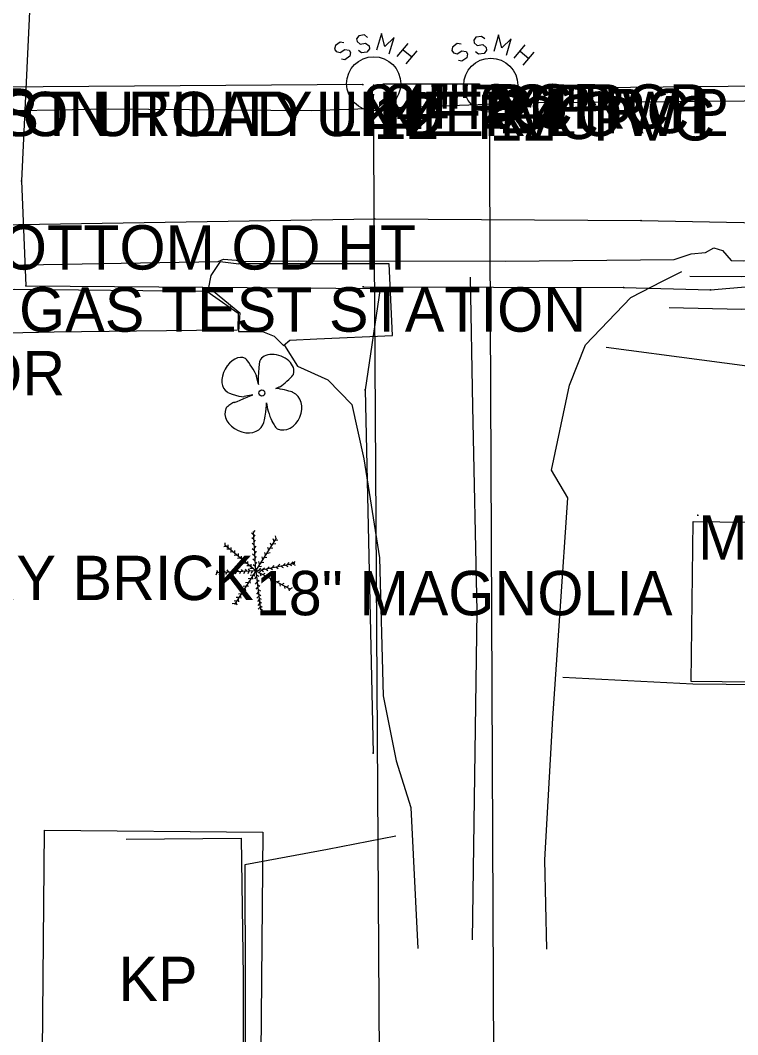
# Model space of a CAD drawing. Extents: x 1304270 to 1306561, y 1876019 to 1876752.
# Drawn here: x 1306257.2 to 1306338, y 1876310 to 1876424.3 of the extents above; entities that cross this region are included whole.
import ezdxf

# ---------------------------------------------------------------- set-up
doc = ezdxf.new("R2010")
doc.units = 0
for name, color, linetype in [('S_BUILDING', 7, 'Continuous'), ('S_BUILDING_ANNOT', 7, 'Continuous'), ('S_DRIVEWAY', 7, 'Continuous'), ('S_EDGE_CONCRETE', 7, 'Continuous'), ('S_EDGE_PAVEMENT', 7, 'Continuous'), ('S_ELECTRIC_UTILITIES_ANNOT', 7, 'Continuous'), ('S_FENCE_ANNOT', 7, 'Continuous'), ('S_FIBER_OPTIC_CABLE', 7, 'Continuous'), ('S_GAS_UTILITIES', 7, 'Continuous'), ('S_MANHOLE_ANNOT', 7, 'Continuous'), ('S_MISC_STRUCTURES_ANNOT', 7, 'Continuous'), ('S_MSC_PT_SYM', 7, 'Continuous'), ('S_PAVEMENT_CROWN', 7, 'Continuous'), ('S_SANITARY_SEWER', 7, 'Continuous'), ('S_SANITARY_SEWER_ANNOT', 7, 'Continuous'), ('S_SIDEWALK', 7, 'Continuous'), ('S_SURVEY_TEXT_ANNOT', 7, 'Continuous'), ('S_TREE', 7, 'Continuous'), ('S_TREE_ANNOT', 7, 'Continuous'), ('S_UTL_PT_SYM', 7, 'Continuous')]:
    doc.layers.add(name, color=color, linetype=linetype)

msp = doc.modelspace()

# ---------------------------------------------------------------- linework, layer by layer
at = {"layer": 'S_BUILDING'}
for points in [[(1306332.98, 1876367.83), (1306353.96, 1876367.59), (1306353.76, 1876349.58), (1306332.78, 1876349.82)], [(1306284.18, 1876299.56), (1306259.59, 1876299.78), (1306259.89, 1876333.06), (1306284.48, 1876332.84)]]:
    msp.add_lwpolyline(points, close=True, dxfattribs=at)
at = {"layer": 'S_DRIVEWAY'}
for points in [[(1306323.18, 1876387.47), (1306344.74, 1876384.62), (1306356.72, 1876379.57), (1306356.54, 1876363.18), (1306355.17, 1876349.22), (1306351.78, 1876349.32), (1306332.95, 1876349.51), (1306318.29, 1876350.28)], [(1306299.5, 1876332.4), (1306291.78, 1876330.88), (1306282.48, 1876329.17), (1306282.52, 1876315.62), (1306282.56, 1876302.07), (1306291.83, 1876303.11), (1306298.15, 1876300.65)]]:
    msp.add_lwpolyline(points, dxfattribs=at)
at = {"layer": 'S_EDGE_CONCRETE'}
for points in [[(1306279.7, 1876397.13), (1306278.64, 1876395.57), (1306278.32, 1876394.02), (1306278.93, 1876393.81), (1306281.92, 1876391.36), (1306281.76, 1876389.26), (1306284.47, 1876389.24), (1306285.76, 1876388.71), (1306286.81, 1876387.68), (1306287.53, 1876388.28), (1306290.57, 1876388.42), (1306299.12, 1876388.8), (1306298.72, 1876396.86), (1306288.66, 1876396.89), (1306281.81, 1876396.86)], [(1306279.7, 1876397.13), (1306281.81, 1876396.86)], [(1306269.08, 1876332.06), (1306282.06, 1876332.17), (1306282.27, 1876316.57), (1306282.31, 1876300.9)]]:
    msp.add_lwpolyline(points, dxfattribs=at)
at = {"layer": 'S_EDGE_PAVEMENT'}
for points in [[(1306165.48, 1876396.19), (1306188.31, 1876396.43), (1306201.55, 1876396.99), (1306203.51, 1876397.54), (1306207.41, 1876397.36), (1306207.63, 1876397.16), (1306215.41, 1876396.62), (1306234.61, 1876396.75), (1306255.38, 1876396.73), (1306279.47, 1876397.14), (1306280.07, 1876397.39), (1306281.48, 1876397.3), (1306281.94, 1876397.15), (1306288.47, 1876397.22), (1306311.84, 1876397.17), (1306330.84, 1876397.38), (1306332.77, 1876398.02), (1306334.38, 1876398.14), (1306335.31, 1876398.67), (1306336.28, 1876398.38), (1306337.28, 1876397.24), (1306338.63, 1876397.21), (1306354.54, 1876397.37)], [(1306316.5, 1876319.67), (1306316.26, 1876329.73), (1306317.19, 1876345.69), (1306318.01, 1876357.74), (1306318.87, 1876370.51), (1306317.01, 1876373.62), (1306319.05, 1876383.21), (1306320.86, 1876387.76), (1306325.95, 1876393.07), (1306329.55, 1876394.92), (1306331.7, 1876396)], [(1306286.94, 1876387.67), (1306288.39, 1876385.33), (1306291.82, 1876383.82), (1306294.54, 1876381.01), (1306295.87, 1876374.92), (1306297.65, 1876363.74), (1306298.05, 1876348.2), (1306299.51, 1876340.88), (1306301.19, 1876335.62), (1306301.96, 1876319.75)]]:
    msp.add_lwpolyline(points, dxfattribs=at)
at = {"layer": 'S_FIBER_OPTIC_CABLE'}
for p, q in [((1306252.11, 1876401.25), (1306297.1, 1876401.93)), ((1306297.1, 1876401.93), (1306327.13, 1876401.75)), ((1306327.13, 1876401.75), (1306345.07, 1876401.41))]:
    msp.add_line(p, q, dxfattribs=at)
at = {"layer": 'S_GAS_UTILITIES'}
for p, q in [((1306258.43, 1876430.5), (1306257.31, 1876406.22)), ((1306257.31, 1876406.22), (1306257.8, 1876394.4)), ((1306257.8, 1876394.4), (1306297.73, 1876394.08)), ((1306295.81, 1876394.3), (1306325.16, 1876394.21)), ((1306297.73, 1876394.08), (1306296.02, 1876382.69)), ((1306325.16, 1876394.21), (1306334.96, 1876393.93)), ((1306334.96, 1876393.93), (1306346.57, 1876394.94)), ((1306296.02, 1876382.69), (1306296.93, 1876341.76))]:
    msp.add_line(p, q, dxfattribs=at)
at = {"layer": 'S_MSC_PT_SYM'}
msp.add_lwpolyline([(1306333.53, 1876368.54), (1306333.53, 1876368.59), (1306333.53, 1876368.54), (1306333.48, 1876368.54), (1306333.53, 1876368.54), (1306333.53, 1876368.49), (1306333.53, 1876368.54), (1306333.58, 1876368.54)], dxfattribs=at)
at = {"layer": 'S_PAVEMENT_CROWN'}
for points in [[(1306053.64, 1876411.74), (1306078.45, 1876411.98), (1306096.34, 1876412.19), (1306114.22, 1876412.39), (1306129.3, 1876412.61), (1306144.38, 1876412.83), (1306159.45, 1876413.06), (1306174.53, 1876413.28), (1306194.7, 1876413.58), (1306214.87, 1876413.88), (1306234.9, 1876413.74), (1306250.98, 1876414.03), (1306267.06, 1876414.33), (1306289.97, 1876414.14), (1306302.49, 1876414.59), (1306315, 1876415.05), (1306334.8, 1876415.21), (1306354.59, 1876415.38)], [(1306308.12, 1876320.71), (1306308.39, 1876339.22), (1306308.66, 1876357.73), (1306308.15, 1876380.81), (1306307.91, 1876395.39)]]:
    msp.add_lwpolyline(points, dxfattribs=at)
at = {"layer": 'S_SANITARY_SEWER'}
for p, q in [((1306292.67, 1876421.46), (1306292.59, 1876421.07)), ((1306293.21, 1876421.85), (1306292.67, 1876421.46)), ((1306293.64, 1876421.77), (1306293.21, 1876421.85)), ((1306299.64, 1876420.22), (1306300.88, 1876421.69)), ((1306306.4, 1876421.69), (1306305.86, 1876421.3)), ((1306306.83, 1876421.61), (1306306.4, 1876421.69)), ((1306312.83, 1876420.06), (1306314.07, 1876421.54)), ((1306292.59, 1876421.07), (1306292.78, 1876420.8)), ((1306292.78, 1876420.8), (1306293.21, 1876420.69)), ((1306293.21, 1876420.69), (1306293.75, 1876421.03)), ((1306293.75, 1876421.03), (1306294.22, 1876420.96)), ((1306294.22, 1876420.96), (1306294.37, 1876420.69)), ((1306294.37, 1876420.69), (1306294.3, 1876420.26)), ((1306300.3, 1876421), (1306301.27, 1876420.18)), ((1306301.85, 1876420.88), (1306300.61, 1876419.41)), ((1306305.86, 1876421.3), (1306305.78, 1876420.92)), ((1306305.78, 1876420.92), (1306305.97, 1876420.64)), ((1306305.97, 1876420.64), (1306306.4, 1876420.53)), ((1306306.4, 1876420.53), (1306306.94, 1876420.88)), ((1306306.94, 1876420.88), (1306307.41, 1876420.8)), ((1306307.41, 1876420.8), (1306307.56, 1876420.53)), ((1306307.56, 1876420.53), (1306307.48, 1876420.1)), ((1306313.49, 1876420.84), (1306314.46, 1876420.02)), ((1306315.04, 1876420.72), (1306313.8, 1876419.25)), ((1306293.75, 1876419.87), (1306293.37, 1876419.95)), ((1306294.3, 1876420.26), (1306293.75, 1876419.87)), ((1306306.94, 1876419.71), (1306306.55, 1876419.79)), ((1306307.48, 1876420.1), (1306306.94, 1876419.71)), ((1306535.55, 1876418.78), (1306311.23, 1876416.59)), ((1306295.77, 1876417.07), (1306233.29, 1876416.64)), ((1306308.91, 1876417.1), (1306298.08, 1876417.12)), ((1306298.44, 1876181.2), (1306296.96, 1876415.93)), ((1306311.04, 1876183.54), (1306310.05, 1876415.77))]:
    msp.add_line(p, q, dxfattribs=at)
for points in [[(1306296.31, 1876422.39), (1306295.96, 1876422.66), (1306295.3, 1876422.58), (1306295.07, 1876422.24), (1306295.11, 1876421.93), (1306295.46, 1876421.62), (1306296.08, 1876421.73), (1306296.47, 1876421.42), (1306296.5, 1876421.11), (1306296.23, 1876420.72), (1306295.61, 1876420.65), (1306295.26, 1876420.92)], [(1306298.75, 1876420.53), (1306299.29, 1876422.39), (1306298.25, 1876421.38), (1306297.86, 1876422.82), (1306297.32, 1876420.96)], [(1306311.94, 1876420.37), (1306312.48, 1876422.23), (1306311.44, 1876421.23), (1306311.05, 1876422.66), (1306310.51, 1876420.8)], [(1306309.5, 1876422.23), (1306309.15, 1876422.5), (1306308.49, 1876422.43), (1306308.26, 1876422.08), (1306308.3, 1876421.77), (1306308.65, 1876421.46), (1306309.27, 1876421.57), (1306309.65, 1876421.26), (1306309.69, 1876420.95), (1306309.42, 1876420.57), (1306308.8, 1876420.49), (1306308.45, 1876420.76)]]:
    msp.add_lwpolyline(points, dxfattribs=at)
for centre in [(1306296.99, 1876417.16), (1306310.18, 1876417)]:
    msp.add_circle(centre, 3.05, dxfattribs=at)
at = {"layer": 'S_SIDEWALK'}
for points in [[(1306332.6, 1876395.5), (1306338.44, 1876395.45), (1306348.81, 1876395.93), (1306349.98, 1876395.68), (1306357.8, 1876395.81)], [(1306218.73, 1876393.56), (1306242.23, 1876393.89), (1306246.62, 1876393.94), (1306256.53, 1876394.01), (1306278.18, 1876393.8), (1306278.83, 1876393.36), (1306281.72, 1876391.3), (1306281.69, 1876389.49)], [(1306330.28, 1876391.97), (1306338.44, 1876391.76), (1306349.3, 1876391.86), (1306357.11, 1876391.89)], [(1306218.81, 1876388.57), (1306242.93, 1876388.89), (1306246.78, 1876388.93), (1306260.98, 1876389.2), (1306270.25, 1876389.34), (1306277.02, 1876389.42), (1306281.65, 1876389.43)]]:
    msp.add_lwpolyline(points, dxfattribs=at)
at = {"layer": 'S_TREE'}
for p, q in [((1306284.02, 1876383.3), (1306283.78, 1876384.19)), ((1306285.97, 1876382.84), (1306286.35, 1876383)), ((1306283.37, 1876382.13), (1306282.4, 1876381.92)), ((1306284.91, 1876381.2), (1306284.99, 1876380.76)), ((1306283.44, 1876366.36), (1306283.22, 1876366.56)), ((1306283.7, 1876362.28), (1306283.43, 1876366.71)), ((1306283.44, 1876366.61), (1306283.63, 1876366.84)), ((1306280.27, 1876365.16), (1306280.27, 1876365.46)), ((1306283.47, 1876365.8), (1306283.25, 1876365.99)), ((1306283.5, 1876365.22), (1306283.28, 1876365.42)), ((1306283.47, 1876366.13), (1306283.65, 1876366.36)), ((1306283.5, 1876365.53), (1306283.69, 1876365.76)), ((1306283.7, 1876362.28), (1306286.04, 1876365.96)), ((1306285.47, 1876365.14), (1306285.38, 1876365.42)), ((1306285.77, 1876365.59), (1306285.68, 1876365.88)), ((1306285.9, 1876365.75), (1306286.2, 1876365.79)), ((1306286.01, 1876365.93), (1306285.92, 1876366.22)), ((1306280.41, 1876365.02), (1306280.11, 1876364.98)), ((1306283.7, 1876362.28), (1306280.23, 1876365.19)), ((1306280.76, 1876364.74), (1306280.46, 1876364.72)), ((1306280.59, 1876364.91), (1306280.59, 1876365.21)), ((1306281.12, 1876364.42), (1306280.82, 1876364.4)), ((1306280.94, 1876364.62), (1306280.94, 1876364.92)), ((1306281.35, 1876364.26), (1306281.35, 1876364.56)), ((1306283.53, 1876364.56), (1306283.3, 1876364.76)), ((1306283.54, 1876364.82), (1306283.73, 1876365.05)), ((1306283.6, 1876364.25), (1306283.79, 1876364.49)), ((1306284.8, 1876364.05), (1306284.71, 1876364.34)), ((1306285.01, 1876364.29), (1306285.31, 1876364.34)), ((1306285.17, 1876364.62), (1306285.08, 1876364.91)), ((1306285.33, 1876364.83), (1306285.63, 1876364.88)), ((1306285.66, 1876365.32), (1306285.95, 1876365.37)), ((1306281.58, 1876364.05), (1306281.28, 1876364.02)), ((1306281.94, 1876363.72), (1306281.64, 1876363.69)), ((1306281.77, 1876363.93), (1306281.77, 1876364.23)), ((1306282.28, 1876363.45), (1306281.98, 1876363.43)), ((1306282.09, 1876363.65), (1306282.09, 1876363.95)), ((1306282.62, 1876363.16), (1306282.32, 1876363.13)), ((1306282.46, 1876363.34), (1306282.46, 1876363.64)), ((1306282.82, 1876363.04), (1306282.82, 1876363.34)), ((1306283.57, 1876363.97), (1306283.34, 1876364.17)), ((1306283.61, 1876363.4), (1306283.38, 1876363.6)), ((1306283.61, 1876363.68), (1306283.8, 1876363.92)), ((1306283.64, 1876363.01), (1306283.83, 1876363.25)), ((1306283.7, 1876362.28), (1306288.12, 1876363.15)), ((1306284.14, 1876363.03), (1306284.05, 1876363.32)), ((1306284.33, 1876363.23), (1306284.62, 1876363.28)), ((1306284.5, 1876363.56), (1306284.41, 1876363.85)), ((1306284.66, 1876363.78), (1306284.96, 1876363.82)), ((1306287.28, 1876362.99), (1306287.48, 1876363.21)), ((1306287.72, 1876363.08), (1306287.93, 1876363.3)), ((1306287.95, 1876363.13), (1306288.15, 1876363.35)), ((1306279.33, 1876362.07), (1306279.19, 1876361.8)), ((1306283.7, 1876362.28), (1306279.24, 1876362.07)), ((1306279.48, 1876362.09), (1306279.31, 1876362.34)), ((1306279.68, 1876362.09), (1306279.54, 1876361.82)), ((1306279.86, 1876362.12), (1306279.69, 1876362.36)), ((1306280.02, 1876362.11), (1306279.88, 1876361.84)), ((1306280.26, 1876362.12), (1306280.09, 1876362.36)), ((1306280.44, 1876362.12), (1306280.3, 1876361.86)), ((1306280.66, 1876362.14), (1306280.49, 1876362.39)), ((1306280.95, 1876362.15), (1306280.81, 1876361.88)), ((1306281.23, 1876362.15), (1306281.06, 1876362.4)), ((1306283.7, 1876362.28), (1306281.31, 1876358.5)), ((1306281.51, 1876362.18), (1306281.37, 1876361.91)), ((1306281.79, 1876362.19), (1306281.62, 1876362.44)), ((1306281.99, 1876362.2), (1306281.86, 1876361.93)), ((1306282.26, 1876362.21), (1306282.09, 1876362.45)), ((1306282.46, 1876362.22), (1306282.33, 1876361.95)), ((1306282.7, 1876362.24), (1306282.53, 1876362.49)), ((1306282.99, 1876362.86), (1306282.69, 1876362.84)), ((1306282.92, 1876362.23), (1306282.79, 1876361.96)), ((1306283.04, 1876362.28), (1306282.87, 1876362.53)), ((1306283.35, 1876362.56), (1306283.05, 1876362.54)), ((1306283.31, 1876362.24), (1306283.17, 1876361.97)), ((1306283.18, 1876362.72), (1306283.18, 1876363.02)), ((1306283.62, 1876362.78), (1306283.39, 1876362.98)), ((1306283.7, 1876362.28), (1306287.61, 1876360.23)), ((1306283.7, 1876362.28), (1306284.23, 1876357.91)), ((1306284.02, 1876362.1), (1306284.29, 1876362.24)), ((1306284.04, 1876362.77), (1306284.34, 1876362.81)), ((1306284.07, 1876362.36), (1306284.27, 1876362.59)), ((1306284.21, 1876362), (1306284.28, 1876361.71)), ((1306284.31, 1876362.4), (1306284.57, 1876362.23)), ((1306284.47, 1876362.42), (1306284.67, 1876362.64)), ((1306284.5, 1876361.87), (1306284.77, 1876362.01)), ((1306284.83, 1876362.47), (1306285.08, 1876362.31)), ((1306285, 1876362.53), (1306285.2, 1876362.75)), ((1306285.35, 1876362.59), (1306285.6, 1876362.43)), ((1306285.57, 1876362.65), (1306285.77, 1876362.88)), ((1306285.95, 1876362.72), (1306286.21, 1876362.56)), ((1306286.2, 1876362.8), (1306286.4, 1876363.02)), ((1306286.53, 1876362.82), (1306286.79, 1876362.66)), ((1306286.79, 1876362.89), (1306287, 1876363.11)), ((1306287.04, 1876362.94), (1306287.3, 1876362.78)), ((1306287.47, 1876363.03), (1306287.72, 1876362.87)), ((1306287.88, 1876363.09), (1306288.13, 1876362.93)), ((1306282.85, 1876360.97), (1306282.55, 1876360.94)), ((1306283.13, 1876361.41), (1306282.83, 1876361.38)), ((1306283, 1876361.18), (1306283.07, 1876360.89)), ((1306283.37, 1876361.78), (1306283.07, 1876361.75)), ((1306283.28, 1876361.62), (1306283.35, 1876361.33)), ((1306283.49, 1876361.96), (1306283.56, 1876361.67)), ((1306283.76, 1876361.6), (1306283.56, 1876361.38)), ((1306283.82, 1876361.02), (1306283.63, 1876360.8)), ((1306283.77, 1876361.85), (1306284.03, 1876361.7)), ((1306283.81, 1876361.3), (1306284.07, 1876361.14)), ((1306284.79, 1876361.7), (1306284.86, 1876361.41)), ((1306285.06, 1876361.57), (1306285.32, 1876361.71)), ((1306285.32, 1876361.42), (1306285.39, 1876361.13)), ((1306285.61, 1876361.29), (1306285.88, 1876361.43)), ((1306285.84, 1876361.15), (1306285.91, 1876360.86)), ((1306286.1, 1876361.03), (1306286.36, 1876361.17)), ((1306286.38, 1876360.85), (1306286.45, 1876360.56)), ((1306286.63, 1876360.76), (1306286.9, 1876360.9)), ((1306282.33, 1876360.13), (1306282.04, 1876360.1)), ((1306282.2, 1876359.88), (1306282.27, 1876359.59)), ((1306282.6, 1876360.55), (1306282.3, 1876360.52)), ((1306282.48, 1876360.34), (1306282.56, 1876360.05)), ((1306282.74, 1876360.77), (1306282.82, 1876360.48)), ((1306283.91, 1876360.46), (1306283.71, 1876360.23)), ((1306283.98, 1876359.89), (1306283.78, 1876359.67)), ((1306283.9, 1876360.73), (1306284.15, 1876360.57)), ((1306283.96, 1876360.18), (1306284.22, 1876360.03)), ((1306286.9, 1876360.6), (1306286.97, 1876360.3)), ((1306287.18, 1876360.48), (1306287.44, 1876360.62)), ((1306287.39, 1876360.34), (1306287.46, 1876360.05)), ((1306287.57, 1876360.27), (1306287.84, 1876360.41)), ((1306281.35, 1876358.59), (1306281.05, 1876358.55)), ((1306281.55, 1876358.89), (1306281.25, 1876358.86)), ((1306281.47, 1876358.75), (1306281.55, 1876358.46)), ((1306281.8, 1876359.3), (1306281.5, 1876359.27)), ((1306281.7, 1876359.1), (1306281.77, 1876358.81)), ((1306282.04, 1876359.68), (1306281.74, 1876359.65)), ((1306281.95, 1876359.5), (1306282.03, 1876359.21)), ((1306284.04, 1876359.44), (1306283.84, 1876359.21)), ((1306284.08, 1876359.05), (1306283.88, 1876358.83)), ((1306284.14, 1876358.61), (1306283.94, 1876358.38)), ((1306284.03, 1876359.67), (1306284.29, 1876359.52)), ((1306284.06, 1876359.24), (1306284.32, 1876359.08)), ((1306284.11, 1876358.83), (1306284.36, 1876358.68)), ((1306284.18, 1876358.19), (1306283.99, 1876357.96)), ((1306284.17, 1876358.37), (1306284.43, 1876358.21)), ((1306284.21, 1876358.03), (1306284.47, 1876357.87))]:
    msp.add_line(p, q, dxfattribs=at)
msp.add_circle((1306284.39, 1876382.32), 0.341, dxfattribs=at)
for centre, major_axis, ratio, start_param, end_param in [((1306281.5, 1876384.33), (-1.03, -1.88), 0.662338, 3.141593, 6.283185), ((1306283.16, 1876385.2), (0.62, -1.01), 0.083512, 0, 3.141593), ((1306286.05, 1876385.2), (1.89, -0.74), 0.673998, 0, 3.141593), ((1306284.09, 1876384.62), (-0.07, -1.33), 0.068203, 3.141593, 6.283185), ((1306287.15, 1876383.73), (-0.798, -0.73), 0.092159, 0, 3.141593), ((1306286.93, 1876382.61), (0.96, -0.23), 0.056001, 0, 3.141593), ((1306281.44, 1876382.18), (0.964, -0.267), 0.113563, 3.141593, 6.283185), ((1306282.34, 1876381.69), (1.04, 0.44), 0.002756, 3.141593, 6.283185), ((1306287.01, 1876380.33), (0.88, 2.05), 0.81717, 3.141593, 6.283185), ((1306282.41, 1876379.66), (2.07, -0.93), 0.760068, 3.141593, 6.283185), ((1306280.82, 1876380.92), (0.477, 0.328), 0.136309, 0, 3.141593), ((1306284.67, 1876380.04), (0.19, 1.31), 0.114148, 3.141593, 5.822668), ((1306285.24, 1876379.99), (0.254, -0.771), 0.051603, 3.141593, 6.283185), ((1306285.82, 1876378.75), (-0.321, 0.467), 0.094289, 0, 3.141593)]:
    msp.add_ellipse(centre, major_axis=major_axis, ratio=ratio, start_param=start_param, end_param=end_param, dxfattribs=at)
at = {"layer": 'S_UTL_PT_SYM'}
for points in [[(1306295.77, 1876417.07), (1306295.77, 1876417.12), (1306295.77, 1876417.07), (1306295.72, 1876417.07), (1306295.77, 1876417.07), (1306295.77, 1876417.02), (1306295.77, 1876417.07), (1306295.82, 1876417.07)], [(1306296.99, 1876417), (1306296.99, 1876417.05), (1306296.99, 1876417), (1306296.94, 1876417), (1306296.99, 1876417), (1306296.99, 1876416.95), (1306296.99, 1876417), (1306297.04, 1876417)], [(1306298.08, 1876417.12), (1306298.08, 1876417.17), (1306298.08, 1876417.12), (1306298.03, 1876417.12), (1306298.08, 1876417.12), (1306298.08, 1876417.07), (1306298.08, 1876417.12), (1306298.13, 1876417.12)], [(1306308.91, 1876417.1), (1306308.91, 1876417.15), (1306308.91, 1876417.1), (1306308.86, 1876417.1), (1306308.91, 1876417.1), (1306308.91, 1876417.05), (1306308.91, 1876417.1), (1306308.96, 1876417.1)], [(1306310.2, 1876416.87), (1306310.2, 1876416.92), (1306310.2, 1876416.87), (1306310.15, 1876416.87), (1306310.2, 1876416.87), (1306310.2, 1876416.82), (1306310.2, 1876416.87), (1306310.25, 1876416.87)], [(1306296.96, 1876415.93), (1306296.96, 1876415.98), (1306296.96, 1876415.93), (1306296.91, 1876415.93), (1306296.96, 1876415.93), (1306296.96, 1876415.88), (1306296.96, 1876415.93), (1306297.01, 1876415.93)], [(1306310.05, 1876415.77), (1306310.05, 1876415.82), (1306310.05, 1876415.77), (1306310, 1876415.77), (1306310.05, 1876415.77), (1306310.05, 1876415.72), (1306310.05, 1876415.77), (1306310.1, 1876415.77)], [(1306311.23, 1876416.59), (1306311.23, 1876416.64), (1306311.23, 1876416.59), (1306311.18, 1876416.59), (1306311.23, 1876416.59), (1306311.23, 1876416.54), (1306311.23, 1876416.59), (1306311.28, 1876416.59)], [(1306257.31, 1876406.22), (1306257.31, 1876406.27), (1306257.31, 1876406.22), (1306257.26, 1876406.22), (1306257.31, 1876406.22), (1306257.31, 1876406.17), (1306257.31, 1876406.22), (1306257.36, 1876406.22)], [(1306297.1, 1876401.93), (1306297.1, 1876401.98), (1306297.1, 1876401.93), (1306297.05, 1876401.93), (1306297.1, 1876401.93), (1306297.1, 1876401.88), (1306297.1, 1876401.93), (1306297.15, 1876401.93)], [(1306327.13, 1876401.75), (1306327.13, 1876401.8), (1306327.13, 1876401.75), (1306327.08, 1876401.75), (1306327.13, 1876401.75), (1306327.13, 1876401.7), (1306327.13, 1876401.75), (1306327.18, 1876401.75)], [(1306257.8, 1876394.4), (1306257.8, 1876394.45), (1306257.8, 1876394.4), (1306257.75, 1876394.4), (1306257.8, 1876394.4), (1306257.8, 1876394.35), (1306257.8, 1876394.4), (1306257.85, 1876394.4)], [(1306295.81, 1876394.3), (1306295.81, 1876394.35), (1306295.81, 1876394.3), (1306295.76, 1876394.3), (1306295.81, 1876394.3), (1306295.81, 1876394.25), (1306295.81, 1876394.3), (1306295.86, 1876394.3)], [(1306297.73, 1876394.08), (1306297.73, 1876394.13), (1306297.73, 1876394.08), (1306297.68, 1876394.08), (1306297.73, 1876394.08), (1306297.73, 1876394.03), (1306297.73, 1876394.08), (1306297.78, 1876394.08)], [(1306325.16, 1876394.21), (1306325.16, 1876394.26), (1306325.16, 1876394.21), (1306325.11, 1876394.21), (1306325.16, 1876394.21), (1306325.16, 1876394.16), (1306325.16, 1876394.21), (1306325.21, 1876394.21)], [(1306334.96, 1876393.93), (1306334.96, 1876393.98), (1306334.96, 1876393.93), (1306334.91, 1876393.93), (1306334.96, 1876393.93), (1306334.96, 1876393.88), (1306334.96, 1876393.93), (1306335.01, 1876393.93)], [(1306296.02, 1876382.69), (1306296.02, 1876382.74), (1306296.02, 1876382.69), (1306295.97, 1876382.69), (1306296.02, 1876382.69), (1306296.02, 1876382.64), (1306296.02, 1876382.69), (1306296.07, 1876382.69)], [(1306296.93, 1876341.76), (1306296.93, 1876341.81), (1306296.93, 1876341.76), (1306296.88, 1876341.76), (1306296.93, 1876341.76), (1306296.93, 1876341.71), (1306296.93, 1876341.76), (1306296.98, 1876341.76)]]:
    msp.add_lwpolyline(points, dxfattribs=at)

# ---------------------------------------------------------------- texts
at = {"layer": 'S_BUILDING_ANNOT'}
msp.add_text('KP', height=5, dxfattribs=at).set_placement((1306268.23, 1876313.81))
at = {"layer": 'S_ELECTRIC_UTILITIES_ANNOT'}
msp.add_text('POINT ON ROAD UNDER LOW L', height=5, dxfattribs=at).set_placement((1306235.12, 1876411.26))
at = {"layer": 'S_FENCE_ANNOT'}
msp.add_text("3'WOODEN/ WOODEN POST  POOR", height=5, dxfattribs=at).set_placement((1306148.39, 1876382.06))
at = {"layer": 'S_MANHOLE_ANNOT'}
msp.add_text('BOTTOM OD HT', height=5, dxfattribs=at).set_placement((1306250.51, 1876396.23))
at = {"layer": 'S_MISC_STRUCTURES_ANNOT'}
msp.add_text('GAS TEST STATION', height=5, dxfattribs=at).set_placement((1306257.03, 1876389.23))
at = {"layer": 'S_SANITARY_SEWER_ANNOT'}
for s, p in [('24" RCP', (1306295.77, 1876412.07)), ('24" RCP', (1306298.08, 1876412.12)), ('24" RCP', (1306308.91, 1876412.1)), ('24" RCP', (1306233.29, 1876411.64)), ('12" PVC', (1306296.96, 1876410.93)), ('12" PVC', (1306310.05, 1876410.77)), ('24" RCP', (1306311.23, 1876411.59))]:
    msp.add_text(s, height=5, dxfattribs=at).set_placement(p)
at = {"layer": 'S_SURVEY_TEXT_ANNOT'}
for s, p in [('LOWEST UTILITY LINE', (1306235.12, 1876411.26)), ('METL CARPORT', (1306333.53, 1876363.54)), ('1STRY BRICK', (1306239.64, 1876358.99))]:
    msp.add_text(s, height=5, dxfattribs=at).set_placement(p)
at = {"layer": 'S_TREE_ANNOT'}
msp.add_text('18" MAGNOLIA', height=5, dxfattribs=at).set_placement((1306283.7, 1876357.28))

doc.saveas('drawing.dxf')
